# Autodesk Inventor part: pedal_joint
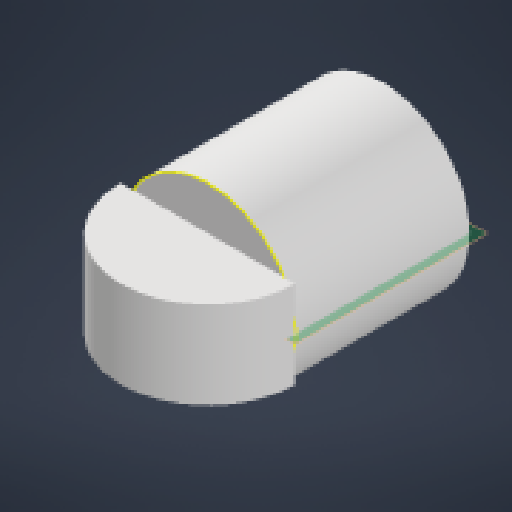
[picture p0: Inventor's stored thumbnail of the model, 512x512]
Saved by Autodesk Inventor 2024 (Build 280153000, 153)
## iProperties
Created: 2023-09
Part Number: pedal_joint
Material: Generic
Document SubType Name: Modeling
Designer: mammothbane
Density: 1 g/cm^3
Appearance: Default
Author: mammothbane
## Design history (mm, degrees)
sketch "Sketch1"
  geometry: C1 r 10 at (0, 0); 1 further point
  constraints: 1 centre point, 1 coincident
  dimensions: "d0" = 20 diameter of C1
extrude "Extrusion1" new body sketch "Sketch1" taper "d2" = 0 deg
sketch "Sketch3"
  geometry: L1 (10, 0)-(-10, 0); A1 r 10 centre (0, 0) between (10, 0) and (-10, 0) reference; 1 further point
  constraints: 2 end point, 2 point on circle, 1 horizontal, 1 line through centre
workplane "Work Plane2"
sketch "Sketch4"
  geometry: L1 (0, 0)-(20, 0) reference; L2 (20, 20)-(20, 0) reference; L3 (0, 0)-(10, 0); L4 (10, 0)-(10, -10); A1 r 10 centre (10, 0) between (0, 0) and (20, 0); 1 further point
  constraints: 4 end point, 3 point on circle, 1 centre point, 1 collinear
extrude "Extrusion2" join sketch "Sketch4" stored distance "d4" = 10; taper "d5" = 0 deg
body "Solid1"
other parameters: "d3" = 90 deg
